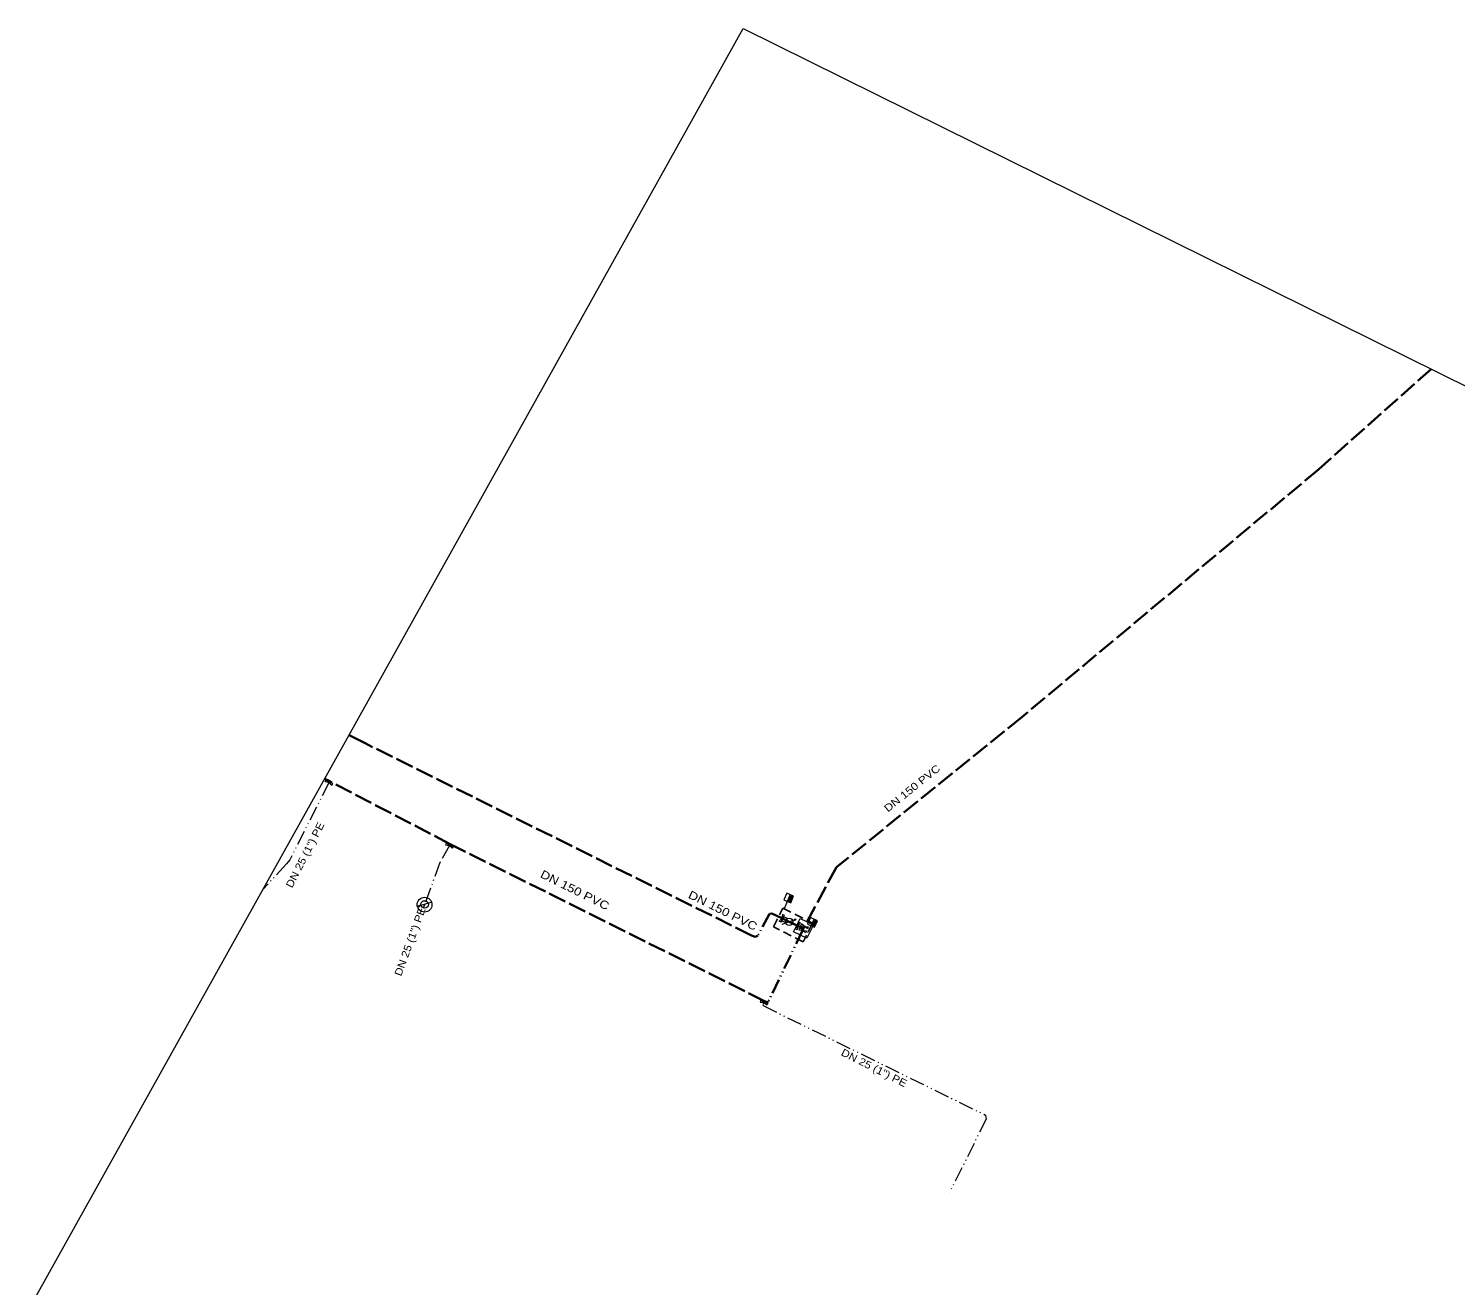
# Model space of a CAD drawing. Extents: x -666776 to -665461, y -1035476 to -1034122.
# Drawn here: x -666775.8 to -666583.7, y -1034290.8 to -1034121.5 of the extents above; entities that cross this region are included whole.
import ezdxf
from ezdxf.enums import TextEntityAlignment as Align

# ---------------------------------------------------------------- set-up
doc = ezdxf.new("R2010")
doc.units = 0
doc.header["$LTSCALE"] = 0.4
for name, pattern in [('DASH_DOUBLE_DOT', [9.2, 5, -1.2, 0.3, -1.2, 0.3, -1.2]), ('LONG_DASHED', [7.5, 6, -1.5]), ('MEDIUM_DASHED', [4.5, 3, -1.5])]:
    doc.linetypes.add(name, pattern=pattern)
for name, color, linetype, lineweight in [('1', 7, 'Continuous', 13), ('10', 7, 'Continuous', 13), ('12', 7, 'Continuous', 13), ('13', 7, 'Continuous', 13), ('21', 7, 'LONG_DASHED', 35), ('22', 7, 'DASH_DOUBLE_DOT', 35), ('32', 7, 'DASH_DOUBLE_DOT', 13), ('52', 7, 'MEDIUM_DASHED', 25)]:
    doc.layers.add(name, color=color, linetype=linetype, lineweight=lineweight)
doc.layers.add('29', color=7, linetype='Continuous')
doc.layers.add('39', color=7, linetype='Continuous')

msp = doc.modelspace()

# ---------------------------------------------------------------- linework, layer by layer
at = {"layer": '1'}
msp.add_lwpolyline([(-666775.826, -1034294.083), (-666679.598, -1034121.513), (-666420.972, -1034249.543), (-666137.785, -1034538.229), (-665871.094, -1034848.91), (-665670.389, -1035030.369), (-665530.17, -1035269.566), (-665461.435, -1035390.539), (-665629.148, -1035475.771), (-665736.374, -1035275.065), (-665821.605, -1035126.598), (-666206.52, -1034821.416), (-666437.468, -1034532.73), (-666634.05, -1034380.689)], close=True, dxfattribs=at)
at = {"layer": '10'}
msp.add_line((-666721.523, -1034239.186), (-666723.439, -1034239.757), dxfattribs=at)
for points in [[(-666734.857, -1034223.176), (-666735.883, -1034222.984), (-666735.746, -1034222.717), (-666734.994, -1034223.443)], [(-666719.663, -1034231.466), (-666718.637, -1034231.654), (-666718.773, -1034231.921), (-666719.527, -1034231.199)], [(-666674.305, -1034240.824), (-666674.463, -1034241.856), (-666674.734, -1034241.727), (-666674.034, -1034240.953)], [(-666671.938, -1034241.369), (-666670.135, -1034242.234), (-666671, -1034244.037), (-666672.803, -1034243.172)], [(-666672.152, -1034241.848), (-666672.31, -1034242.88), (-666672.581, -1034242.751), (-666671.881, -1034241.977)], [(-666672.114, -1034242.895), (-666671.082, -1034243.052), (-666671.21, -1034243.323), (-666671.985, -1034242.624)], [(-666671.865, -1034242.363), (-666670.83, -1034242.495), (-666670.951, -1034242.769), (-666671.743, -1034242.089)], [(-666677.327, -1034252.646), (-666676.293, -1034252.794), (-666676.419, -1034253.065), (-666677.201, -1034252.375)]]:
    msp.add_lwpolyline(points, close=True, dxfattribs=at)
msp.add_lwpolyline([(-666723.141, -1034239.775), (-666723.439, -1034239.757), (-666723.199, -1034239.578)], dxfattribs=at)
for centre, radius in [((-666722.4969, -1034239.514), 0.9994), ((-666722.481, -1034239.471), 0.5)]:
    msp.add_circle(centre, radius, dxfattribs=at)
at = {"layer": '12'}
msp.add_line((-666674.326, -1034242.157), (-666672.448, -1034241.473), dxfattribs=at)
msp.add_lwpolyline([(-666672.748, -1034241.471), (-666672.448, -1034241.473), (-666672.677, -1034241.666)], dxfattribs=at)
msp.add_circle((-666673.3864, -1034241.8144), 0.5, dxfattribs=at)
at = {"layer": '13'}
for p, q in [((-666674.05, -1034240.01), (-666673.261, -1034238.172)), ((-666670.89, -1034243.27), (-666670.049, -1034241.456))]:
    msp.add_line(p, q, dxfattribs=at)
for points in [[(-666673.725, -1034237.973), (-666674.109, -1034238.87), (-666673.183, -1034239.268), (-666672.798, -1034238.371)], [(-666673.211, -1034238.298), (-666672.924, -1034238.421), (-666673.233, -1034239.142), (-666673.52, -1034239.019)], [(-666673.163, -1034238.419), (-666673.399, -1034238.97), (-666673.282, -1034239.021), (-666673.045, -1034238.469)], [(-666674.168, -1034241.126), (-666674.404, -1034241.678), (-666673.852, -1034241.914), (-666673.616, -1034241.362)], [(-666670.506, -1034241.244), (-666670.916, -1034242.129), (-666670.002, -1034242.553), (-666669.591, -1034241.668)], [(-666670.002, -1034241.583), (-666669.719, -1034241.714), (-666670.049, -1034242.426), (-666670.332, -1034242.294)], [(-666669.957, -1034241.705), (-666670.21, -1034242.25), (-666670.093, -1034242.303), (-666669.841, -1034241.759)]]:
    msp.add_lwpolyline(points, close=True, dxfattribs=at)
at = {"layer": '21'}
for p, q in [((-666735.26, -1034222.89), (-666735.936, -1034222.546)), ((-666719.03, -1034231.37), (-666735.26, -1034222.89)), ((-666676.707, -1034252.492), (-666719.03, -1034231.37)), ((-666671.347, -1034242.429), (-666671.469, -1034242.703))]:
    msp.add_line(p, q, dxfattribs=at)
for points in [[(-666586.962, -1034167.371), (-666602.11, -1034180.89), (-666642.09, -1034214.26), (-666667.032, -1034234.464), (-666671.347, -1034242.429)], [(-666678.457, -1034243.656), (-666730.509, -1034217.773), (-666732.659, -1034216.67)]]:
    msp.add_lwpolyline(points, dxfattribs=at)
at = {"layer": '22'}
for p, q in [((-666673.386, -1034241.814), (-666674.384, -1034241.34)), ((-666672.231, -1034242.364), (-666673.386, -1034241.814)), ((-666671.469, -1034242.703), (-666672.231, -1034242.364)), ((-666671.469, -1034242.703), (-666671.598, -1034242.974))]:
    msp.add_line(p, q, dxfattribs=at)
for points in [[(-666674.384, -1034241.34), (-666675.755, -1034240.689), (-666676.046, -1034240.751), (-666677.618, -1034243.689), (-666677.987, -1034243.846), (-666678.457, -1034243.656), (-666678.457, -1034243.656)], [(-666671.598, -1034242.974), (-666676.212, -1034252.601), (-666676.366, -1034252.658), (-666676.707, -1034252.492)]]:
    msp.add_lwpolyline(points, dxfattribs=at)
at = {"layer": '32'}
for p, q in [((-666735.26, -1034222.89), (-666735.37, -1034223.08)), ((-666719.03, -1034231.37), (-666719.15, -1034231.56)), ((-666722.497, -1034239.514), (-666722.668, -1034239.983))]:
    msp.add_line(p, q, dxfattribs=at)
for points in [[(-666735.37, -1034223.08), (-666740.655, -1034233.465), (-666741.074, -1034234.02), (-666744.226, -1034237.412)], [(-666719.15, -1034231.56), (-666720.429, -1034233.847), (-666722.481, -1034239.471), (-666722.497, -1034239.514)], [(-666676.81, -1034252.72), (-666676.933, -1034252.982), (-666676.91, -1034253.102), (-666646.948, -1034267.868), (-666646.859, -1034268.381), (-666651.808, -1034278.267)], [(-666676.707, -1034252.492), (-666676.81, -1034252.72), (-666676.81, -1034252.72)]]:
    msp.add_lwpolyline(points, dxfattribs=at)
at = {"layer": '52'}
msp.add_lwpolyline([(-666674.245, -1034239.992), (-666670.244, -1034241.991), (-666671.498, -1034244.502), (-666675.499, -1034242.503)], close=True, dxfattribs=at)

# ---------------------------------------------------------------- texts
at = {"layer": '29', "width": 1.2}
for height, rotation, p in [(1, 38.828, (-666656.5325, -1034224.2254)), (1.1, 333.478, (-666702.5016, -1034238.03)), (1.1, 333.561, (-666682.5729, -1034240.7917))]:
    msp.add_text('DN 150 PVC', height=height, rotation=rotation, dxfattribs=at).set_placement(p, align=Align.CENTER)
at = {"layer": '39', "width": 1.15}
for rotation, p in [(63.028, (-666738.138, -1034233.0278)), (69.953, (-666723.9907, -1034244.6654)), (333.204, (-666662.1854, -1034261.934))]:
    msp.add_text('DN 25 (1") PE', height=1, rotation=rotation, dxfattribs=at).set_placement(p, align=Align.CENTER)

doc.saveas('drawing.dxf')
